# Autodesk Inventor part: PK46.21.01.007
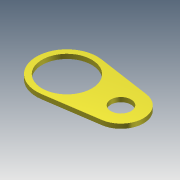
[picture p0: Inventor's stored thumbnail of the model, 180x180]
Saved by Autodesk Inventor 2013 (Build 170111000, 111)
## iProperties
Created: 2005-04
Part Number: PK46.21.01.007
Material: Steel, Mild
Document SubType Name: Modeling
Designer: salex
Manufacturer: Standard
Standards Organization: Custom
Density: 7.86 g/cm^3
Author: salex
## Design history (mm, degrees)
sketch "Эскиз1"
  geometry: L1 (19.688, 133.557)-(254.583, 98.931); L2 (19.688, -133.557)-(254.583, -98.931); C1 r 110.5 at (0, 0); C2 r 45 at (240, 0); A1 r 135 centre (0, 0) between (19.688, 133.557) and (19.688, -133.557); A2 r 100 centre (240, 0) between (254.583, -98.931) and (254.583, 98.931)
  constraints: 4 centre point, 4 end point, 4 point on circle, 4 tangent, 2 coincident, 1 other
  dimensions: "d0" = 221 diameter of C1; "d1" = 0 vertical distance of C2.centre C1.centre; "d2" = 240 distance of C2.centre C1.centre; "d3" = 135 radius of A1; "d4" = 100 radius of A2; "d5" = 90 diameter of C2
extrude "Выдавливание1" new body sketch "Эскиз1" distance "d6" = 20; taper "d7" = 0 deg
body "Solid1"
